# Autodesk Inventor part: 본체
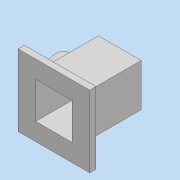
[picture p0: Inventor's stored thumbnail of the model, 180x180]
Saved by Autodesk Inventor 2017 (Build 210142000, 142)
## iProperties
Part Number: 본체
Material: 일반
Document SubType Name: Modeling
Designer: MRC
Density: 1 g/cm^3
Appearance: 기본값
Author: MRC
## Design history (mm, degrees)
sketch "스케치1"
  geometry: L1 (57, 57)-(-57, 57); L2 (-57, 57)-(-57, -57); L3 (-57, -57)-(57, -57); L4 (57, -57)-(57, 57); L5 (57, 57)-(-57, -57); L6 (-57, 57)-(57, -57); 1 further point
  constraints: 12 end point, 2 midpoint, 2 parallel, 1 horizontal, 1 perpendicular
  dimensions: "d0" = 114 distance of L3.end L2.end; "d1" = 114 distance of L2.end L1.end
extrude "돌출1" new body sketch "스케치1" distance "d2" = 10; taper "d3" = 0 deg
sketch "스케치2"
  geometry: L1 (-34, -34)-(34, -34); L2 (34, -34)-(34, 34); L3 (34, 34)-(-34, 34); L4 (-34, 34)-(-34, -34); L5 (-34, -34)-(34, 34); L6 (34, -34)-(-34, 34); 1 further point
  constraints: 12 end point, 2 midpoint, 2 parallel, 1 horizontal, 1 perpendicular
  dimensions: "d4" = 68 distance of L3.end L2.end; "d5" = 68 distance of L2.end L1.end
extrude "돌출2" join sketch "스케치2" distance "d6" = 95; taper "d7" = 0 deg
sketch "스케치3"
  geometry: L1 (-29, -29)-(29, -29); L2 (29, -29)-(29, 29); L3 (29, 29)-(-29, 29); L4 (-29, 29)-(-29, -29); L5 (-29, -29)-(29, 29); L6 (29, -29)-(-29, 29); 1 further point
  constraints: 12 end point, 2 midpoint, 2 parallel, 1 horizontal, 1 perpendicular
  dimensions: "d8" = 58 distance of L3.end L2.end; "d9" = 58 distance of L2.end L1.end
extrude "돌출3" cut sketch "스케치3" distance "d10" = 100; taper "d11" = 0 deg
node "작업 평면1"
sketch "스케치4"
  geometry: C1 r 20 at (0, 0); 1 further point
  constraints: 1 centre point, 1 coincident
  dimensions: "d13" = 40 diameter of C1
extrude "돌출4" join sketch "스케치4" stored distance "d14" = 100; taper "d15" = 8 deg
hole "구멍1" diameter "d18" = 22.835; stored, may be unused: countersink angle "d22" = 90 deg, drill point angle "d24" = 118 deg; dims "d16" = 10, "d17" = 10, "d19" = 50, "d20" = 4, "d21" = 2, "d23" = 59.3
sketch "스케치5"
  geometry: L1 (-23, -10)-(91, -10) reference; C1 r 28.5 at (34, 42); 2 further points
  constraints: 1 centre point, 1 midpoint, 1 vertical alignment
  dimensions: "d25" = 57 diameter of C1; "d26" = 52 distance from line of C1.centre L1
extrude "돌출5" join sketch "스케치5" distance "d27" = 15; taper "d28" = 0 deg
hole "구멍2" diameter "d31" = 30; stored, may be unused: countersink angle "d35" = 90 deg, drill point angle "d37" = 0 deg; dims "d29" = 10, "d30" = 10, "d32" = 50, "d33" = 35, "d34" = 17, "d36" = 30
sketch "스케치6"
  geometry: L1 (-57, -52)-(57, -52) reference; C1 r 15 at (0, 0) reference; 3 further points
  constraints: 1 midpoint, 1 vertical alignment
  dimensions: "d38" = 22 distance of point (0, 22) C1.centre
hole "구멍3" sketch "스케치6" at (0, 22) diameter "d39" = 3.242; stored, may be unused: countersink angle "d43" = 90 deg, drill point angle "d45" = 118 deg; dims "d40" = 8, "d41" = 35, "d42" = 17, "d44" = 10
node "솔리드1"
